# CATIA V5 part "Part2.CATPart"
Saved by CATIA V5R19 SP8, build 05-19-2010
Part number: Poignee2
Bounding box of the stored display mesh (mm): x -18 to 30, y -19.79 to 19.79, z -19.79 to 19.79
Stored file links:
  G:\EU_thinkMotion\CFAO_2010\SIL_groupe2\SIL_groupe2\msauret\Brevet_Sauret_parametre\Part2.CATPart
  F:\Brevet_Sauret paramétré\Product3.CATProduct
  G:\EU_thinkMotion\CFAO_2010\SIL_groupe2\SIL_groupe2\msauret\Brevet_Sauret_parametre\squelette.CATPart
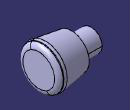
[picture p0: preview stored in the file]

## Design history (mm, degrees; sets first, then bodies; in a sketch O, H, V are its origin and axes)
Set1
  Plane1: linked copy from another document
  Point1: linked copy from another document
  Plane2: linked copy from another document
  Line1: linked copy from another document
  Plane3: linked copy from another document
  Plane4: linked copy from another document
Body1 (main body)
  Sketch1 on Plane1, origin (0, 0, 0), H (-1, 0, 0), V (0, 0, 1)
    line L1 (0, 0) -> (0, -16.1971)
    line L2 (0, -16.1971) -> (-25, -20)
    line L3 (-25, -20) -> (-30, -18)
    line L4 (-30, -18) -> (-30, 0)
    line L5 (-30, 0) -> (0, 0)
    reference projected point E1 (0, 0) from Point1
    reference intersected line E2 through (-30, 0) direction (0, -1) from Plane2
    distance E1 L1 = 0
    distance E2 L4 = 0
    vertical: L1 V, L4 V
    horizontal: L5 H
  Shaft1: profile Sketch1, axis Line1, angle 360
  Sketch2 on Plane3, origin (0, 0, 0), H (0, 1, 0), V (0, 0, 1)
    circle A1 centre (0, 0) radius 10
  Pad1: profile Sketch2, direction (1, 0, 0), up to Plane4
  Fillet1: radius 5, on face of Shaft1 from Sketch1.L3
